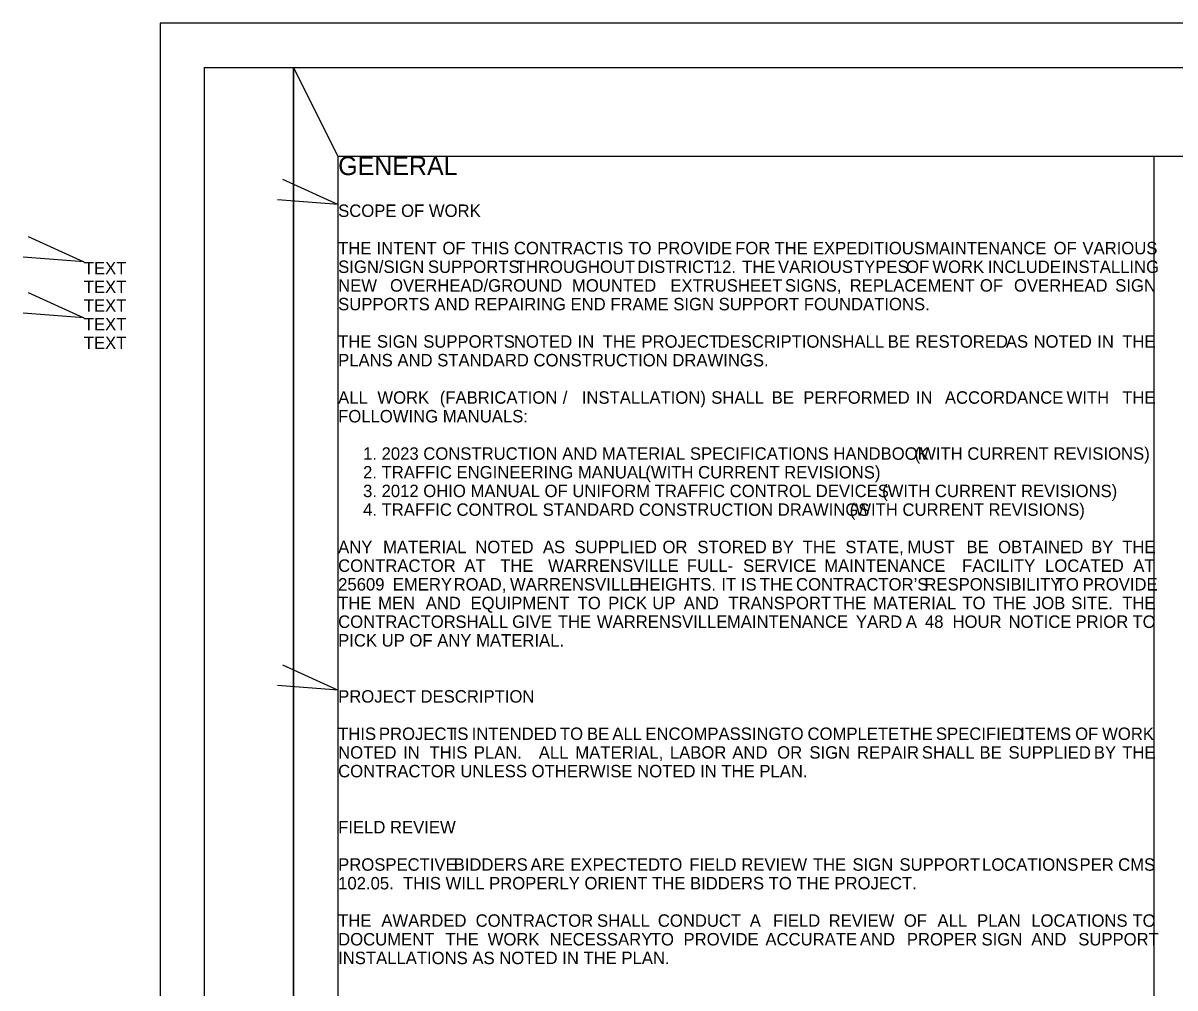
# Model space of a CAD drawing. Extents: x -1.5 to 44.5, y 0 to 22.
# Drawn here: x -1.54 to 11.4, y 11.15 to 22 of the extents above; entities that cross this region are included whole.
import ezdxf

# ---------------------------------------------------------------- set-up
doc = ezdxf.new("R2010")
doc.units = 0
for name, color, linetype in [('SC_Scratch1', 7, 'Continuous'), ('SH_Border', 7, 'Continuous'), ('SH_Cut_Line', 7, 'Continuous'), ('SH_Text', 7, 'Continuous')]:
    doc.layers.add(name, color=color, linetype=linetype)

msp = doc.modelspace()

# ---------------------------------------------------------------- linework, layer by layer
at = {"layer": 'SC_Scratch1'}
for p, q in [((2, 20.5), (1.5, 21.5)), ((2, 1.5), (2, 20.5)), ((31.5, 20.5), (2, 20.5)), ((11.167, 1.5), (11.167, 20.5))]:
    msp.add_line(p, q, dxfattribs=at)
for points in [[(1.376, 20.246), (2, 19.96), (1.317, 20.012)], [(-1.482, 19.601), (-0.858, 19.315), (-1.541, 19.367)], [(-1.482, 18.971), (-0.858, 18.685), (-1.541, 18.737)], [(1.376, 14.786), (2, 14.5), (1.317, 14.552)]]:
    msp.add_lwpolyline(points, dxfattribs=at)
at = {"layer": 'SH_Border'}
for points in [[(0.5, 21.5), (1.5, 21.5), (1.5, 0.5), (0.5, 0.5)], [(1.5, 21.5), (33.5, 21.5), (33.5, 0.5), (1.5, 0.5)]]:
    msp.add_lwpolyline(points, close=True, dxfattribs=at)
at = {"layer": 'SH_Cut_Line'}
msp.add_lwpolyline([(0, 0), (34, 0), (34, 22), (0, 22)], close=True, dxfattribs=at)

# ---------------------------------------------------------------- texts
at = {"layer": 'SH_Text'}
for s, height, p in [('GENERAL', 0.21, (2, 20.29)), ('SCOPE OF WORK', 0.14, (2, 19.82)), ('THE ', 0.14, (2, 19.4)), ('INTENT ', 0.14, (2.431, 19.4)), ('OF ', 0.14, (3.172, 19.4)), ('THIS ', 0.14, (3.496, 19.4)), ('CONTRACT ', 0.14, (3.975, 19.4)), ('IS ', 0.14, (5.027, 19.4)), ('TO ', 0.14, (5.261, 19.4)), ('PROVIDE ', 0.14, (5.585, 19.4)), ('FOR ', 0.14, (6.461, 19.4)), ('THE ', 0.14, (6.903, 19.4)), ('EXPEDITIOUS ', 0.14, (7.334, 19.4)), ('MAINTENANCE ', 0.14, (8.596, 19.4)), ('OF ', 0.14, (10.039, 19.4)), ('VARIOUS ', 0.14, (10.363, 19.4)), ('TEXT', 0.14, (-0.858, 19.175)), ('SIGN/SIGN ', 0.14, (2, 19.19)), ('SUPPORTS ', 0.14, (3.009, 19.19)), ('THROUGHOUT ', 0.14, (3.995, 19.19)), ('DISTRICT ', 0.14, (5.363, 19.19)), ('12. ', 0.14, (6.21, 19.19)), ('THE ', 0.14, (6.539, 19.19)), ('VARIOUS ', 0.14, (6.942, 19.19)), ('TYPES ', 0.14, (7.796, 19.19)), ('OF ', 0.14, (8.381, 19.19)), ('WORK ', 0.14, (8.676, 19.19)), ('INCLUDE ', 0.14, (9.299, 19.19)), ('INSTALLING ', 0.14, (10.131, 19.19)), ('TEXT', 0.14, (-0.858, 18.965)), ('NEW ', 0.14, (2, 18.98)), ('OVERHEAD/GROUND ', 0.14, (2.583, 18.98)), ('MOUNTED ', 0.14, (4.627, 18.98)), ('EXTRUSHEET ', 0.14, (5.732, 18.98)), ('SIGNS, ', 0.14, (7.02, 18.98)), ('REPLACEMENT ', 0.14, (7.748, 18.98)), ('OF ', 0.14, (9.211, 18.98)), ('OVERHEAD ', 0.14, (9.594, 18.98)), ('SIGN ', 0.14, (10.731, 18.98)), ('SUPPORTS AND REPAIRING END FRAME SIGN SUPPORT FOUNDATIONS.', 0.14, (2, 18.77)), ('TEXT', 0.14, (-0.858, 18.755)), ('TEXT', 0.14, (-0.858, 18.545)), ('TEXT', 0.14, (-0.858, 18.335)), ('THE ', 0.14, (2, 18.35)), ('SIGN ', 0.14, (2.436, 18.35)), ('SUPPORTS ', 0.14, (2.956, 18.35)), ('NOTED ', 0.14, (3.975, 18.35)), ('IN ', 0.14, (4.69, 18.35)), ('THE ', 0.14, (4.972, 18.35)), ('PROJECT ', 0.14, (5.408, 18.35)), ('DESCRIPTION ', 0.14, (6.263, 18.35)), ('SHALL ', 0.14, (7.541, 18.35)), ('BE ', 0.14, (8.175, 18.35)), ('RESTORED ', 0.14, (8.486, 18.35)), ('AS ', 0.14, (9.503, 18.35)), ('NOTED ', 0.14, (9.813, 18.35)), ('IN ', 0.14, (10.529, 18.35)), ('THE ', 0.14, (10.81, 18.35)), ('PLANS AND STANDARD CONSTRUCTION DRAWINGS.', 0.14, (2, 18.14)), ('WORK ', 0.14, (2.441, 17.72)), ('(FABRICATION ', 0.14, (3.142, 17.72)), ('/ ', 0.14, (4.524, 17.72)), ('INSTALLATION) ', 0.14, (4.738, 17.72)), ('SHALL ', 0.14, (6.192, 17.72)), ('PERFORMED ', 0.14, (7.226, 17.72)), ('ACCORDANCE ', 0.14, (8.817, 17.72)), ('ALL ', 0.14, (2, 17.72)), ('BE ', 0.14, (6.871, 17.72)), ('IN ', 0.14, (8.491, 17.72)), ('WITH ', 0.14, (10.185, 17.72)), ('THE ', 0.14, (10.81, 17.72)), ('FOLLOWING MANUALS:', 0.14, (2, 17.51)), ('1. 2023 CONSTRUCTION AND MATERIAL SPECIFICATIONS HANDBOOK', 0.14, (2.28, 17.09)), ('(WITH CURRENT REVISIONS)', 0.14, (8.477, 17.09)), ('2. TRAFFIC ENGINEERING MANUAL', 0.14, (2.28, 16.88)), (' (WITH CURRENT REVISIONS)', 0.14, (5.4, 16.88)), ('3. 2012 OHIO MANUAL OF UNIFORM TRAFFIC CONTROL DEVICES', 0.14, (2.28, 16.67)), ('(WITH CURRENT REVISIONS)', 0.14, (8.112, 16.67)), ('4. TRAFFIC CONTROL STANDARD CONSTRUCTION DRAWINGS', 0.14, (2.28, 16.46)), ('(WITH CURRENT REVISIONS)', 0.14, (7.748, 16.46)), ('ANY ', 0.14, (2, 16.04)), ('MATERIAL ', 0.14, (2.505, 16.04)), ('NOTED ', 0.14, (3.541, 16.04)), ('AS ', 0.14, (4.301, 16.04)), ('SUPPLIED ', 0.14, (4.656, 16.04)), ('OR ', 0.14, (5.644, 16.04)), ('STORED ', 0.14, (6.036, 16.04)), ('BY ', 0.14, (6.871, 16.04)), ('THE ', 0.14, (7.219, 16.04)), ('STATE, ', 0.14, (7.699, 16.04)), ('MUST ', 0.14, (8.396, 16.04)), ('BE ', 0.14, (9.06, 16.04)), ('OBTAINED ', 0.14, (9.415, 16.04)), ('BY ', 0.14, (10.461, 16.04)), ('THE ', 0.14, (10.81, 16.04)), ('CONTRACTOR ', 0.14, (2, 15.83)), ('AT ', 0.14, (3.418, 15.83)), ('THE ', 0.14, (3.82, 15.83)), ('WARRENSVILLE ', 0.14, (4.359, 15.83)), ('FULL-', 0.14, (5.918, 15.83)), ('SERVICE ', 0.14, (6.55, 15.83)), ('MAINTENANCE ', 0.14, (7.461, 15.83)), ('FACILITY ', 0.14, (9.011, 15.83)), ('LOCATED ', 0.14, (9.943, 15.83)), ('AT ', 0.14, (10.934, 15.83)), ('25609 ', 0.14, (2, 15.62)), ('EMERY ', 0.14, (2.614, 15.62)), ('ROAD, ', 0.14, (3.297, 15.62)), ('WARRENSVILLE ', 0.14, (3.931, 15.62)), ('HEIGHTS.  ', 0.14, (5.361, 15.62)), ('IT ', 0.14, (6.306, 15.62)), ('IS ', 0.14, (6.525, 15.62)), ('THE ', 0.14, (6.737, 15.62)), ('CONTRACTOR’S ', 0.14, (7.145, 15.62)), ('RESPONSIBILITY ', 0.14, (8.587, 15.62)), ('TO ', 0.14, (10.063, 15.62)), ('PROVIDE ', 0.14, (10.365, 15.62)), ('THE ', 0.14, (2, 15.41)), ('MEN ', 0.14, (2.449, 15.41)), ('AND ', 0.14, (2.984, 15.41)), ('EQUIPMENT ', 0.14, (3.487, 15.41)), ('TO ', 0.14, (4.691, 15.41)), ('PICK ', 0.14, (5.034, 15.41)), ('UP ', 0.14, (5.53, 15.41)), ('AND ', 0.14, (5.883, 15.41)), ('TRANSPORT ', 0.14, (6.385, 15.41)), ('THE ', 0.14, (7.559, 15.41)), ('MATERIAL ', 0.14, (8.008, 15.41)), ('TO ', 0.14, (9.014, 15.41)), ('THE ', 0.14, (9.357, 15.41)), ('JOB ', 0.14, (9.806, 15.41)), ('SITE.  ', 0.14, (10.237, 15.41)), ('THE ', 0.14, (10.81, 15.41)), ('CONTRACTOR ', 0.14, (2, 15.2)), ('SHALL ', 0.14, (3.318, 15.2)), ('GIVE ', 0.14, (3.955, 15.2)), ('THE ', 0.14, (4.469, 15.2)), ('WARRENSVILLE ', 0.14, (4.907, 15.2)), ('MAINTENANCE ', 0.14, (6.368, 15.2)), ('YARD ', 0.14, (7.818, 15.2)), ('A ', 0.14, (8.379, 15.2)), ('48 ', 0.14, (8.593, 15.2)), ('HOUR ', 0.14, (8.903, 15.2)), ('NOTICE ', 0.14, (9.532, 15.2)), ('PRIOR ', 0.14, (10.285, 15.2)), ('TO ', 0.14, (10.925, 15.2)), ('PICK UP OF ANY MATERIAL.', 0.14, (2, 14.99)), ('PROJECT DESCRIPTION', 0.14, (2, 14.36)), ('THIS ', 0.14, (2, 13.94)), ('PROJECT ', 0.14, (2.458, 13.94)), ('IS ', 0.14, (3.287, 13.94)), ('INTENDED ', 0.14, (3.5, 13.94)), ('TO ', 0.14, (4.492, 13.94)), ('BE ', 0.14, (4.796, 13.94)), ('ALL ', 0.14, (5.081, 13.94)), ('ENCOMPASSING ', 0.14, (5.452, 13.94)), ('TO ', 0.14, (6.97, 13.94)), ('COMPLETE ', 0.14, (7.274, 13.94)), ('THE ', 0.14, (8.307, 13.94)), ('SPECIFIED ', 0.14, (8.717, 13.94)), ('ITEMS ', 0.14, (9.664, 13.94)), ('OF ', 0.14, (10.281, 13.94)), ('WORK ', 0.14, (10.584, 13.94)), ('NOTED ', 0.14, (2, 13.73)), ('IN ', 0.14, (2.73, 13.73)), ('THIS ', 0.14, (3.026, 13.73)), ('PLAN.   ', 0.14, (3.524, 13.73)), ('ALL ', 0.14, (4.254, 13.73)), ('MATERIAL, ', 0.14, (4.665, 13.73)), ('LABOR ', 0.14, (5.727, 13.73)), ('AND ', 0.14, (6.429, 13.73)), ('OR ', 0.14, (6.933, 13.73)), ('SIGN ', 0.14, (7.295, 13.73)), ('REPAIR ', 0.14, (7.83, 13.73)), ('SHALL ', 0.14, (8.558, 13.73)), ('BE ', 0.14, (9.206, 13.73)), ('SUPPLIED ', 0.14, (9.532, 13.73)), ('BY ', 0.14, (10.491, 13.73)), ('THE ', 0.14, (10.81, 13.73)), ('CONTRACTOR UNLESS OTHERWISE NOTED IN THE PLAN. ', 0.14, (2, 13.52)), ('FIELD REVIEW', 0.14, (2, 12.89)), ('PROSPECTIVE ', 0.14, (2, 12.47)), ('BIDDERS ', 0.14, (3.298, 12.47)), ('ARE ', 0.14, (4.161, 12.47)), ('EXPECTED ', 0.14, (4.608, 12.47)), ('TO ', 0.14, (5.607, 12.47)), ('FIELD ', 0.14, (5.945, 12.47)), ('REVIEW ', 0.14, (6.53, 12.47)), ('THE ', 0.14, (7.334, 12.47)), ('SIGN ', 0.14, (7.779, 12.47)), ('SUPPORT ', 0.14, (8.307, 12.47)), ('LOCATIONS ', 0.14, (9.235, 12.47)), ('PER ', 0.14, (10.33, 12.47)), ('CMS ', 0.14, (10.764, 12.47)), ('102.05.  THIS WILL PROPERLY ORIENT THE BIDDERS TO THE PROJECT.', 0.14, (2, 12.26)), ('THE ', 0.14, (2, 11.84)), ('AWARDED ', 0.14, (2.485, 11.84)), ('CONTRACTOR ', 0.14, (3.545, 11.84)), ('SHALL ', 0.14, (4.909, 11.84)), ('CONDUCT ', 0.14, (5.592, 11.84)), ('A ', 0.14, (6.625, 11.84)), ('FIELD ', 0.14, (6.886, 11.84)), ('REVIEW ', 0.14, (7.511, 11.84)), ('OF ', 0.14, (8.356, 11.84)), ('ALL ', 0.14, (8.734, 11.84)), ('PLAN ', 0.14, (9.179, 11.84)), ('LOCATIONS ', 0.14, (9.788, 11.84)), ('TO ', 0.14, (10.925, 11.84)), ('DOCUMENT ', 0.14, (2, 11.63)), ('THE ', 0.14, (3.205, 11.63)), ('WORK ', 0.14, (3.68, 11.63)), ('NECESSARY ', 0.14, (4.375, 11.63)), ('TO ', 0.14, (5.513, 11.63)), ('PROVIDE ', 0.14, (5.881, 11.63)), ('ACCURATE ', 0.14, (6.801, 11.63)), ('AND ', 0.14, (7.862, 11.63)), ('PROPER ', 0.14, (8.39, 11.63)), ('SIGN ', 0.14, (9.229, 11.63)), ('AND ', 0.14, (9.788, 11.63)), ('SUPPORT ', 0.14, (10.316, 11.63)), ('INSTALLATIONS AS NOTED IN THE PLAN.', 0.14, (2, 11.42))]:
    msp.add_text(s, height=height, dxfattribs=at).set_placement(p)

doc.saveas('drawing.dxf')
